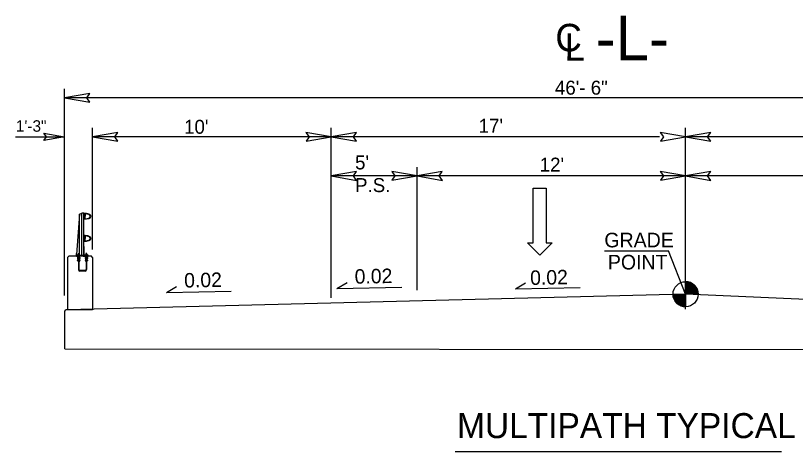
# Model space of a CAD drawing. Extents: x 1733676 to 1734289, y 540979 to 541226.
# Drawn here: x 1733960.89 to 1733995.74, y 541121.97 to 541141.46 of the extents above; entities that cross this region are included whole.
import ezdxf

# ---------------------------------------------------------------- set-up
doc = ezdxf.new("R2010")
doc.units = 0
for name, color, linetype in [('Prop Dimension', 7, 'Continuous'), ('Prop Lane Arrow CELL', 7, 'Continuous'), ('Prop Terminator CELL', 7, 'Continuous'), ('Typical Bridge Rail Two Bar CELL', 7, 'Continuous'), ('Typical Grade Point Symbol CELL', 7, 'Continuous'), ('Typical Pavement Slope CELL', 7, 'Continuous'), ('Typical Pavement Slope Information CELL', 7, 'Continuous'), ('Typical Slope Point Local CELL', 7, 'Continuous'), ('Typical Text Centerline CELL', 7, 'Continuous'), ('Typical Text General CELL', 7, 'Continuous'), ('Typical Text Grade Point CELL', 7, 'Continuous'), ('Typical Text Label CELL', 7, 'Continuous')]:
    doc.layers.add(name, color=color, linetype=linetype)

msp = doc.modelspace()

# ---------------------------------------------------------------- linework, layer by layer
at = {"layer": 'Prop Dimension'}
for p, q in [((1733963.084, 541128.948), (1733963.084, 541138.185)), ((1734008.084, 541137.785), (1733963.084, 541137.785)), ((1733964.334, 541130.995), (1733964.334, 541136.435)), ((1733975.001, 541128.839), (1733975.001, 541136.435)), ((1733990.834, 541128.328), (1733990.834, 541136.435)), ((1733960.893, 541136.035), (1733963.084, 541136.035)), ((1733975.001, 541136.035), (1733964.334, 541136.035)), ((1733989.668, 541136.035), (1733973.834, 541136.035)), ((1734006.834, 541136.035), (1733990.834, 541136.035)), ((1733978.834, 541129.179), (1733978.834, 541134.685)), ((1733978.834, 541134.285), (1733975.001, 541134.285)), ((1733990.834, 541134.285), (1733978.834, 541134.285)), ((1734002.834, 541134.285), (1733990.834, 541134.285)), ((1733987.214, 541130.939), (1733990.074, 541130.939)), ((1733990.834, 541129.001), (1733990.074, 541130.939))]:
    msp.add_line(p, q, dxfattribs=at)
at = {"layer": 'Prop Lane Arrow CELL'}
for p, q in [((1733984.03, 541131.294), (1733984.03, 541133.744)), ((1733984.03, 541133.744), (1733984.608, 541133.744)), ((1733984.608, 541133.744), (1733984.608, 541131.294)), ((1733984.328, 541130.743), (1733983.768, 541131.294)), ((1733983.768, 541131.294), (1733984.03, 541131.294)), ((1733984.87, 541131.294), (1733984.328, 541130.743)), ((1733984.608, 541131.294), (1733984.87, 541131.294))]:
    msp.add_line(p, q, dxfattribs=at)
at = {"layer": 'Prop Terminator CELL'}
for points in [[(1733964.209, 541137.979), (1733963.084, 541137.785), (1733964.216, 541137.585), (1733964.072, 541137.785)], [(1733962.159, 541136.194), (1733963.084, 541136.035), (1733962.154, 541135.87), (1733962.272, 541136.035)], [(1733965.459, 541136.229), (1733964.334, 541136.035), (1733965.466, 541135.835), (1733965.322, 541136.035)], [(1733973.876, 541135.841), (1733975.001, 541136.035), (1733973.87, 541136.235), (1733974.014, 541136.035)], [(1733976.126, 541136.229), (1733975.001, 541136.035), (1733976.132, 541135.835), (1733975.989, 541136.035)], [(1733989.709, 541135.841), (1733990.834, 541136.035), (1733989.703, 541136.235), (1733989.847, 541136.035)], [(1733991.959, 541136.229), (1733990.834, 541136.035), (1733991.966, 541135.835), (1733991.822, 541136.035)], [(1733976.126, 541134.479), (1733975.001, 541134.285), (1733976.132, 541134.085), (1733975.989, 541134.285)], [(1733977.709, 541134.091), (1733978.834, 541134.285), (1733977.703, 541134.485), (1733977.847, 541134.285)], [(1733979.959, 541134.479), (1733978.834, 541134.285), (1733979.966, 541134.085), (1733979.822, 541134.285)], [(1733989.709, 541134.091), (1733990.834, 541134.285), (1733989.703, 541134.485), (1733989.847, 541134.285)], [(1733991.959, 541134.479), (1733990.834, 541134.285), (1733991.966, 541134.085), (1733991.822, 541134.285)]]:
    msp.add_lwpolyline(points, close=True, dxfattribs=at)
at = {"layer": 'Typical Bridge Rail Two Bar CELL'}
for p, q in [((1733963.746, 541132.579), (1733963.615, 541130.77)), ((1733963.746, 541132.579), (1733963.86, 541132.616)), ((1733963.746, 541130.733), (1733963.746, 541132.579)), ((1733963.936, 541132.616), (1733963.86, 541132.616)), ((1733963.86, 541130.733), (1733963.86, 541132.616)), ((1733963.936, 541130.733), (1733963.936, 541132.616)), ((1733963.999, 541132.585), (1733963.999, 541132.483)), ((1733963.999, 541132.38), (1733963.999, 541132.483)), ((1733963.746, 541131.715), (1733963.742, 541131.715)), ((1733963.999, 541131.598), (1733963.999, 541131.496)), ((1733963.999, 541131.393), (1733963.999, 541131.496)), ((1733963.615, 541130.733), (1733963.615, 541130.77)), ((1733963.618, 541130.791), (1733963.618, 541130.824)), ((1733963.687, 541130.649), (1733963.687, 541130.733)), ((1733963.731, 541130.809), (1733963.688, 541130.809)), ((1733963.688, 541130.809), (1733963.688, 541130.773)), ((1733963.731, 541130.773), (1733963.731, 541130.809)), ((1733963.731, 541130.649), (1733963.731, 541130.733)), ((1733964.035, 541130.659), (1733964.035, 541130.742)), ((1733964.08, 541130.819), (1733964.037, 541130.819)), ((1733964.037, 541130.819), (1733964.037, 541130.783)), ((1733964.08, 541130.783), (1733964.08, 541130.819)), ((1733964.082, 541130.659), (1733964.082, 541130.742)), ((1733963.265, 541130.695), (1733963.216, 541130.646)), ((1733963.216, 541130.646), (1733963.216, 541128.301)), ((1733964.286, 541130.695), (1733963.265, 541130.695)), ((1733963.759, 541130.659), (1733963.658, 541130.659)), ((1733963.759, 541130.648), (1733963.658, 541130.648)), ((1733963.7, 541130.614), (1733963.658, 541130.614)), ((1733963.7, 541130.603), (1733963.658, 541130.603)), ((1733963.7, 541130.57), (1733963.658, 541130.57)), ((1733963.7, 541130.559), (1733963.658, 541130.559)), ((1733963.7, 541130.526), (1733963.658, 541130.526)), ((1733963.7, 541130.514), (1733963.658, 541130.514)), ((1733963.7, 541130.481), (1733963.658, 541130.481)), ((1733963.7, 541130.47), (1733963.658, 541130.47)), ((1733963.7, 541130.636), (1733963.681, 541130.636)), ((1733963.7, 541130.625), (1733963.681, 541130.625)), ((1733963.7, 541130.592), (1733963.681, 541130.592)), ((1733963.7, 541130.581), (1733963.681, 541130.581)), ((1733963.7, 541130.548), (1733963.681, 541130.548)), ((1733963.7, 541130.537), (1733963.681, 541130.537)), ((1733963.7, 541130.503), (1733963.681, 541130.503)), ((1733963.7, 541130.492), (1733963.681, 541130.492)), ((1733963.717, 541130.637), (1733963.7, 541130.637)), ((1733963.7, 541130.637), (1733963.7, 541130.106)), ((1733963.717, 541130.637), (1733963.717, 541130.106)), ((1733963.736, 541130.636), (1733963.717, 541130.636)), ((1733963.736, 541130.625), (1733963.717, 541130.625)), ((1733963.759, 541130.614), (1733963.717, 541130.614)), ((1733963.759, 541130.603), (1733963.717, 541130.603)), ((1733963.736, 541130.592), (1733963.717, 541130.592)), ((1733963.736, 541130.581), (1733963.717, 541130.581)), ((1733963.759, 541130.57), (1733963.717, 541130.57)), ((1733963.759, 541130.559), (1733963.717, 541130.559)), ((1733963.736, 541130.548), (1733963.717, 541130.548)), ((1733963.736, 541130.537), (1733963.717, 541130.537)), ((1733963.759, 541130.526), (1733963.717, 541130.526)), ((1733963.759, 541130.514), (1733963.717, 541130.514)), ((1733963.736, 541130.503), (1733963.717, 541130.503)), ((1733963.736, 541130.492), (1733963.717, 541130.492)), ((1733963.759, 541130.481), (1733963.717, 541130.481)), ((1733963.759, 541130.47), (1733963.717, 541130.47)), ((1733964.107, 541130.659), (1733964.007, 541130.659)), ((1733964.107, 541130.648), (1733964.007, 541130.648)), ((1733964.049, 541130.614), (1733964.007, 541130.614)), ((1733964.049, 541130.603), (1733964.007, 541130.603)), ((1733964.049, 541130.57), (1733964.007, 541130.57)), ((1733964.049, 541130.559), (1733964.007, 541130.559)), ((1733964.049, 541130.526), (1733964.007, 541130.526)), ((1733964.049, 541130.514), (1733964.007, 541130.514)), ((1733964.049, 541130.481), (1733964.007, 541130.481)), ((1733964.049, 541130.47), (1733964.007, 541130.47)), ((1733964.049, 541130.636), (1733964.029, 541130.636)), ((1733964.049, 541130.625), (1733964.029, 541130.625)), ((1733964.049, 541130.592), (1733964.029, 541130.592)), ((1733964.049, 541130.581), (1733964.029, 541130.581)), ((1733964.049, 541130.548), (1733964.029, 541130.548)), ((1733964.049, 541130.537), (1733964.029, 541130.537)), ((1733964.049, 541130.503), (1733964.029, 541130.503)), ((1733964.049, 541130.492), (1733964.029, 541130.492)), ((1733964.049, 541130.637), (1733964.049, 541130.106)), ((1733964.065, 541130.636), (1733964.049, 541130.636)), ((1733964.065, 541130.637), (1733964.065, 541130.106)), ((1733964.085, 541130.636), (1733964.065, 541130.636)), ((1733964.085, 541130.625), (1733964.065, 541130.625)), ((1733964.107, 541130.614), (1733964.065, 541130.614)), ((1733964.107, 541130.603), (1733964.065, 541130.603)), ((1733964.085, 541130.592), (1733964.065, 541130.592)), ((1733964.085, 541130.581), (1733964.065, 541130.581)), ((1733964.107, 541130.57), (1733964.065, 541130.57)), ((1733964.107, 541130.559), (1733964.065, 541130.559)), ((1733964.085, 541130.548), (1733964.065, 541130.548)), ((1733964.085, 541130.537), (1733964.065, 541130.537)), ((1733964.107, 541130.526), (1733964.065, 541130.526)), ((1733964.107, 541130.514), (1733964.065, 541130.514)), ((1733964.085, 541130.503), (1733964.065, 541130.503)), ((1733964.085, 541130.492), (1733964.065, 541130.492)), ((1733964.107, 541130.481), (1733964.065, 541130.481)), ((1733964.107, 541130.47), (1733964.065, 541130.47)), ((1733964.334, 541130.646), (1733964.286, 541130.695)), ((1733964.334, 541130.646), (1733964.334, 541128.301)), ((1733963.995, 541130.053), (1733963.77, 541130.053)), ((1733963.995, 541130.036), (1733963.77, 541130.036)), ((1733963.096, 541128.248), (1733963.145, 541128.301)), ((1733963.226, 541128.301), (1733963.145, 541128.301)), ((1733964.334, 541128.301), (1733963.226, 541128.301))]:
    msp.add_line(p, q, dxfattribs=at)
for points in [[(1733963.936, 541132.352), (1733963.936, 541132.401), (1733963.956, 541132.401), (1733963.956, 541132.393), (1733963.954, 541132.393), (1733963.954, 541132.372), (1733963.986, 541132.372), (1733963.99, 541132.404), (1733963.99, 541132.483), (1733963.99, 541132.561), (1733963.986, 541132.593), (1733963.954, 541132.593), (1733963.954, 541132.572), (1733963.956, 541132.572), (1733963.956, 541132.564), (1733963.936, 541132.564), (1733963.936, 541132.613)], [(1733963.936, 541131.365), (1733963.936, 541131.414), (1733963.956, 541131.414), (1733963.956, 541131.406), (1733963.954, 541131.406), (1733963.954, 541131.385), (1733963.986, 541131.385), (1733963.99, 541131.417), (1733963.99, 541131.496), (1733963.99, 541131.574), (1733963.986, 541131.605), (1733963.954, 541131.605), (1733963.954, 541131.585), (1733963.956, 541131.585), (1733963.956, 541131.577), (1733963.936, 541131.577), (1733963.936, 541131.626)], [(1733964.129, 541130.695), (1733964.129, 541130.742), (1733963.955, 541130.742), (1733963.955, 541131.129), (1733963.936, 541131.129), (1733963.936, 541130.733), (1733963.624, 541130.733), (1733963.624, 541130.76), (1733963.615, 541130.76), (1733963.615, 541130.695), (1733963.765, 541130.695), (1733963.765, 541130.721), (1733963.917, 541130.721), (1733963.917, 541130.695), (1733964.129, 541130.695)], [(1733963.752, 541130.732), (1733963.752, 541130.741), (1733963.709, 541130.741), (1733963.667, 541130.741), (1733963.667, 541130.732)], [(1733963.741, 541130.741), (1733963.741, 541130.768), (1733963.736, 541130.773), (1733963.683, 541130.773), (1733963.678, 541130.768), (1733963.678, 541130.741), (1733963.741, 541130.741), (1733963.72, 541130.741), (1733963.72, 541130.768), (1733963.726, 541130.773), (1733963.72, 541130.768), (1733963.715, 541130.773), (1733963.704, 541130.773), (1733963.699, 541130.768), (1733963.699, 541130.741), (1733963.699, 541130.768), (1733963.693, 541130.773)], [(1733964.102, 541130.742), (1733964.102, 541130.75), (1733964.059, 541130.75), (1733964.016, 541130.75), (1733964.016, 541130.742)], [(1733964.09, 541130.75), (1733964.09, 541130.777), (1733964.085, 541130.783), (1733964.032, 541130.783), (1733964.027, 541130.777), (1733964.027, 541130.75), (1733964.09, 541130.75), (1733964.069, 541130.75), (1733964.069, 541130.777), (1733964.075, 541130.783), (1733964.069, 541130.777), (1733964.064, 541130.783), (1733964.053, 541130.783), (1733964.048, 541130.777), (1733964.048, 541130.75), (1733964.048, 541130.777), (1733964.043, 541130.783)], [(1733963.658, 541130.659), (1733963.658, 541130.648), (1733963.681, 541130.636), (1733963.681, 541130.625), (1733963.658, 541130.614), (1733963.658, 541130.603), (1733963.681, 541130.592), (1733963.681, 541130.581), (1733963.658, 541130.57), (1733963.658, 541130.559), (1733963.681, 541130.548), (1733963.681, 541130.537), (1733963.658, 541130.526), (1733963.658, 541130.514), (1733963.681, 541130.503), (1733963.681, 541130.492), (1733963.658, 541130.481), (1733963.658, 541130.47)], [(1733963.759, 541130.659), (1733963.759, 541130.648), (1733963.737, 541130.636), (1733963.737, 541130.625), (1733963.759, 541130.614), (1733963.759, 541130.603), (1733963.737, 541130.592), (1733963.737, 541130.581), (1733963.759, 541130.57), (1733963.759, 541130.559), (1733963.737, 541130.548), (1733963.737, 541130.537), (1733963.759, 541130.526), (1733963.759, 541130.514), (1733963.737, 541130.503), (1733963.737, 541130.492), (1733963.759, 541130.481), (1733963.759, 541130.47)], [(1733964.007, 541130.659), (1733964.007, 541130.648), (1733964.029, 541130.636), (1733964.029, 541130.625), (1733964.007, 541130.614), (1733964.007, 541130.603), (1733964.029, 541130.592), (1733964.029, 541130.581), (1733964.007, 541130.57), (1733964.007, 541130.559), (1733964.029, 541130.548), (1733964.029, 541130.537), (1733964.007, 541130.526), (1733964.007, 541130.514), (1733964.029, 541130.503), (1733964.029, 541130.492), (1733964.007, 541130.481), (1733964.007, 541130.47)], [(1733964.107, 541130.659), (1733964.107, 541130.648), (1733964.085, 541130.636), (1733964.085, 541130.625), (1733964.107, 541130.614), (1733964.107, 541130.603), (1733964.085, 541130.592), (1733964.085, 541130.581), (1733964.107, 541130.57), (1733964.107, 541130.559), (1733964.085, 541130.548), (1733964.085, 541130.537), (1733964.107, 541130.526), (1733964.107, 541130.514), (1733964.085, 541130.503), (1733964.085, 541130.492), (1733964.107, 541130.481), (1733964.107, 541130.47)]]:
    msp.add_lwpolyline(points, dxfattribs=at)
for centre in [(1733963.667, 541130.498), (1733964.098, 541130.498)]:
    msp.add_circle(centre, 0.00834, dxfattribs=at)
for centre, radius, start, end in [((1733964.007, 541132.585), 0.00783, 90, 180), ((1733964.007, 541132.38), 0.00783, 180, 270), ((1733964.007, 541131.598), 0.00783, 90, 180), ((1733964.007, 541131.393), 0.00783, 180, 270), ((1733963.77, 541130.106), 0.07, 180, 270), ((1733963.77, 541130.106), 0.0534, 180, 270), ((1733963.995, 541130.106), 0.0534, 270, 0), ((1733963.995, 541130.106), 0.07, 270, 0)]:
    msp.add_arc(centre, radius, start, end, dxfattribs=at)
for centre, major_axis, ratio, start_param, end_param in [((1733963.935, 541132.483), (0.334, 0), 0.39036, 6.282787, 7.853967), ((1733963.935, 541132.483), (0.334, 0), 0.39036, 4.712404, 6.282787), ((1733964.007, 541132.483), (0.222, 0), 0.495501, 6.282718, 7.853881), ((1733964.007, 541132.483), (0.222, 0), 0.495501, 4.712489, 6.282718), ((1733963.935, 541131.495), (0.334, 0), 0.39036, 6.282787, 7.853967), ((1733963.935, 541131.495), (0.334, 0), 0.39036, 4.712404, 6.282787), ((1733964.007, 541131.495), (0.222, 0), 0.495501, 6.282718, 7.853881), ((1733964.007, 541131.495), (0.222, 0), 0.495501, 4.712489, 6.282718)]:
    msp.add_ellipse(centre, major_axis=major_axis, ratio=ratio, start_param=start_param, end_param=end_param, dxfattribs=at)
at = {"layer": 'Typical Grade Point Symbol CELL'}
for p, q in [((1733990.834, 541129.001), (1733990.834, 541129.561)), ((1733990.275, 541129.001), (1733990.834, 541129.001)), ((1733990.833, 541128.442), (1733990.834, 541129.001)), ((1733990.834, 541129.001), (1733990.833, 541128.442)), ((1733991.394, 541129.001), (1733990.834, 541129.001))]:
    msp.add_line(p, q, dxfattribs=at)
for points in [[(1733990.839, 541129.561), (1733990.839, 541129.561), (1733990.839, 541129.001)], [(1733990.851, 541129.561), (1733990.851, 541129.001)], [(1733990.862, 541129.559), (1733990.862, 541129.001)], [(1733990.873, 541129.559), (1733990.873, 541129.001)], [(1733990.884, 541129.558), (1733990.884, 541129.001)], [(1733990.895, 541129.557), (1733990.895, 541129.001)], [(1733990.907, 541129.556), (1733990.907, 541129.001)], [(1733990.918, 541129.554), (1733990.918, 541129.001)], [(1733990.929, 541129.553), (1733990.929, 541129.001)], [(1733990.94, 541129.551), (1733990.94, 541129.001)], [(1733990.951, 541129.548), (1733990.951, 541129.001)], [(1733990.962, 541129.546), (1733990.962, 541129.001)], [(1733990.974, 541129.543), (1733990.974, 541129.001)], [(1733990.985, 541129.539), (1733990.985, 541129.001)], [(1733990.996, 541129.537), (1733990.996, 541129.001)], [(1733991.007, 541129.533), (1733991.007, 541129.001)], [(1733991.018, 541129.529), (1733991.018, 541129.001)], [(1733991.03, 541129.526), (1733991.03, 541129.001)], [(1733991.041, 541129.521), (1733991.041, 541129.001)], [(1733991.052, 541129.516), (1733991.052, 541129.001)], [(1733991.063, 541129.511), (1733991.063, 541129.001)], [(1733991.074, 541129.506), (1733991.074, 541129.001)], [(1733991.086, 541129.501), (1733991.086, 541129.001)], [(1733991.097, 541129.495), (1733991.097, 541129.001)], [(1733991.108, 541129.488), (1733991.108, 541129.001)], [(1733991.119, 541129.482), (1733991.119, 541129.001)], [(1733991.13, 541129.476), (1733991.13, 541129.001)], [(1733991.141, 541129.469), (1733991.141, 541129.001)], [(1733991.153, 541129.461), (1733991.153, 541129.001)], [(1733991.164, 541129.452), (1733991.164, 541129.001)], [(1733991.175, 541129.445), (1733991.175, 541129.001)], [(1733991.186, 541129.436), (1733991.186, 541129.001)], [(1733991.197, 541129.426), (1733991.197, 541129.001)], [(1733991.209, 541129.416), (1733991.209, 541129.001)], [(1733991.22, 541129.406), (1733991.22, 541129.001)], [(1733991.231, 541129.395), (1733991.231, 541129.001)], [(1733991.242, 541129.384), (1733991.242, 541129.001)], [(1733991.253, 541129.372), (1733991.253, 541129.001)], [(1733991.265, 541129.358), (1733991.265, 541129.001)], [(1733991.276, 541129.344), (1733991.276, 541129.001)], [(1733990.277, 541129.001), (1733990.277, 541128.94)], [(1733990.289, 541129.001), (1733990.289, 541128.874)], [(1733990.3, 541129.001), (1733990.3, 541128.834)], [(1733990.311, 541129.001), (1733990.311, 541128.801)], [(1733990.322, 541129.001), (1733990.322, 541128.775)], [(1733990.333, 541129.001), (1733990.333, 541128.751)], [(1733990.345, 541129.001), (1733990.345, 541128.73)], [(1733990.356, 541129.001), (1733990.356, 541128.71)], [(1733990.367, 541129.001), (1733990.367, 541128.693)], [(1733990.378, 541129.001), (1733990.378, 541128.677)], [(1733990.389, 541129.001), (1733990.389, 541128.662)], [(1733990.4, 541129.001), (1733990.4, 541128.648)], [(1733990.412, 541129.001), (1733990.412, 541128.634)], [(1733990.423, 541129.001), (1733990.423, 541128.622)], [(1733990.434, 541129.001), (1733990.434, 541128.609)], [(1733990.445, 541129.001), (1733990.445, 541128.598)], [(1733990.456, 541129.001), (1733990.456, 541128.588)], [(1733990.468, 541129.001), (1733990.468, 541128.578)], [(1733990.479, 541129.001), (1733990.479, 541128.568)], [(1733990.49, 541129.001), (1733990.49, 541128.56)], [(1733990.501, 541129.001), (1733990.501, 541128.551)], [(1733990.512, 541129.001), (1733990.512, 541128.544)], [(1733990.524, 541129.001), (1733990.524, 541128.536)], [(1733990.535, 541129.001), (1733990.535, 541128.529)], [(1733990.546, 541129.001), (1733990.546, 541128.521)], [(1733990.557, 541129.001), (1733990.557, 541128.515)], [(1733990.568, 541129.001), (1733990.568, 541128.509)], [(1733990.58, 541129.001), (1733990.58, 541128.502)], [(1733990.591, 541129.001), (1733990.591, 541128.498)], [(1733990.602, 541129.001), (1733990.602, 541128.493)], [(1733990.613, 541129.001), (1733990.613, 541128.488)], [(1733990.624, 541129.001), (1733990.624, 541128.483)], [(1733990.635, 541129.001), (1733990.635, 541128.478)], [(1733990.647, 541129.001), (1733990.647, 541128.474)], [(1733990.658, 541129.001), (1733990.658, 541128.47)], [(1733990.669, 541129.001), (1733990.669, 541128.466)], [(1733990.68, 541129.001), (1733990.68, 541128.464)], [(1733990.691, 541129.001), (1733990.691, 541128.46)], [(1733990.703, 541129.001), (1733990.703, 541128.458)], [(1733990.714, 541129.001), (1733990.714, 541128.455)], [(1733990.725, 541129.001), (1733990.725, 541128.453)], [(1733990.736, 541129.001), (1733990.736, 541128.45)], [(1733990.747, 541129.001), (1733990.747, 541128.449)], [(1733990.759, 541129.001), (1733990.759, 541128.447)], [(1733990.77, 541129.001), (1733990.77, 541128.445)], [(1733990.781, 541129.001), (1733990.781, 541128.444)], [(1733990.792, 541129.001), (1733990.792, 541128.443)], [(1733990.803, 541129.001), (1733990.803, 541128.443)], [(1733990.815, 541129.001), (1733990.815, 541128.442)], [(1733990.826, 541129.001), (1733990.826, 541128.442), (1733990.826, 541128.442)], [(1733991.287, 541129.329), (1733991.287, 541129.001)], [(1733991.298, 541129.313), (1733991.298, 541129.001)], [(1733991.309, 541129.296), (1733991.309, 541129.001)], [(1733991.321, 541129.277), (1733991.321, 541129.001)], [(1733991.332, 541129.257), (1733991.332, 541129.001)], [(1733991.343, 541129.234), (1733991.343, 541129.001)], [(1733991.354, 541129.207), (1733991.354, 541129.001)], [(1733991.365, 541129.176), (1733991.365, 541129.001)], [(1733991.376, 541129.138), (1733991.376, 541129.001)], [(1733991.388, 541129.081), (1733991.388, 541129.001)]]:
    msp.add_lwpolyline(points, dxfattribs=at)
msp.add_circle((1733990.834, 541129.001), 0.559, dxfattribs=at)
for start, end in [(359.9905, 89.9905), (179.9905, 269.9905)]:
    msp.add_arc((1733990.834, 541129.001), 0.559, start, end, dxfattribs=at)
at = {"layer": 'Typical Pavement Slope CELL'}
for p, q in [((1733990.834, 541129.001), (1733963.226, 541128.301)), ((1734007.955, 541128.262), (1733990.834, 541129.001))]:
    msp.add_line(p, q, dxfattribs=at)
at = {"layer": 'Typical Pavement Slope Information CELL'}
for p, q in [((1733967.637, 541129.077), (1733968.086, 541129.349)), ((1733975.256, 541129.25), (1733975.705, 541129.522)), ((1733983.237, 541129.236), (1733983.686, 541129.507)), ((1733967.637, 541129.077), (1733970.532, 541129.135)), ((1733975.256, 541129.25), (1733978.15, 541129.308)), ((1733983.237, 541129.236), (1733986.131, 541129.294))]:
    msp.add_line(p, q, dxfattribs=at)
at = {"layer": 'Typical Slope Point Local CELL'}
for q in [(1733963.096, 541128.248), (1734008.084, 541126.524)]:
    msp.add_line((1733963.096, 541126.563), q, dxfattribs=at)
at = {"layer": 'Typical Text Label CELL'}
msp.add_line((1733980.541, 541121.971), (1733995.126, 541121.971), dxfattribs=at)

# ---------------------------------------------------------------- texts
at = {"layer": 'Typical Pavement Slope Information CELL'}
for p in [(1733976.052, 541129.467), (1733983.895, 541129.412), (1733968.433, 541129.294)]:
    msp.add_text('0.02', height=0.6476, rotation=1.1457, dxfattribs=at).set_placement(p)
at = {"layer": 'Typical Slope Point Local CELL'}
for s, height, p in [('46\'- 6"', 0.6249, (1733984.996, 541137.921)), ('1\'-3"', 0.5141, (1733960.905, 541136.264)), ("10'", 0.6249, (1733968.423, 541136.172)), ("17'", 0.6249, (1733981.587, 541136.216)), (" 5'", 0.6249, (1733975.831, 541134.579)), ("12'", 0.6249, (1733984.316, 541134.48)), (' P.S.', 0.6249, (1733975.831, 541133.564))]:
    msp.add_text(s, height=height, rotation=360, dxfattribs=at).set_placement(p)
at = {"layer": 'Typical Text Centerline CELL'}
for s, height, p in [('-L-', 2, (1733986.82, 541139.456)), ('C', 1.23, (1733985.014, 541139.857))]:
    msp.add_text(s, height=height, dxfattribs=at).set_placement(p)
msp.add_text('L', height=1.231, rotation=359.9469, dxfattribs=at).set_placement((1733985.423, 541139.437))
at = {"layer": 'Typical Text General CELL'}
msp.add_text('MULTIPATH TYPICAL', height=1.11936, dxfattribs=at).set_placement((1733980.621, 541122.565))
at = {"layer": 'Typical Text Grade Point CELL'}
for s, p in [('GRADE', (1733987.206, 541131.095)), ('POINT', (1733987.363, 541130.106))]:
    msp.add_text(s, height=0.6525, dxfattribs=at).set_placement(p)

doc.saveas('drawing.dxf')
